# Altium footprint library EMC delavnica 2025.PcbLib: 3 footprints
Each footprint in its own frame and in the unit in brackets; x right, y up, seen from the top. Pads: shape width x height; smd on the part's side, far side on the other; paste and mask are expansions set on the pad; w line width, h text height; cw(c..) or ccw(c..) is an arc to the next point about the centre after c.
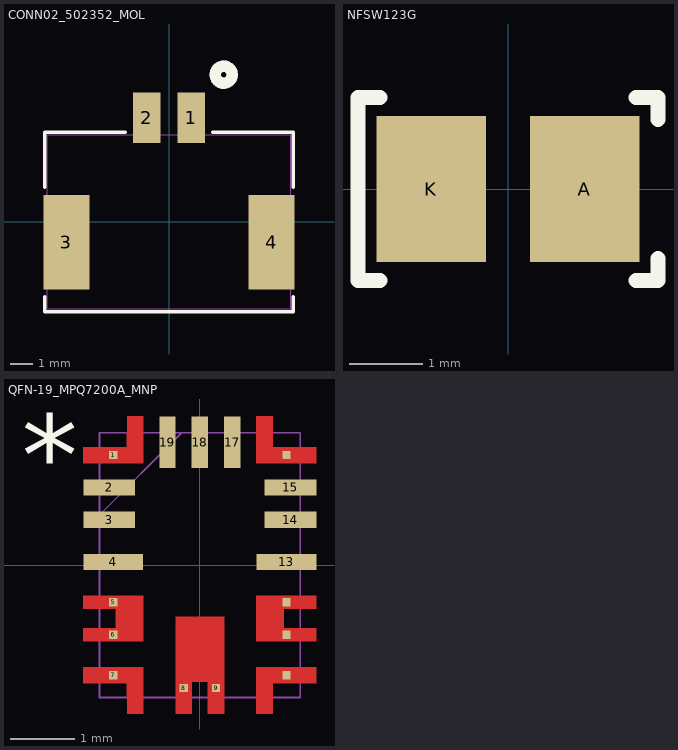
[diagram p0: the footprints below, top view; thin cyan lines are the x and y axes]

## CONN02_502352_MOL [mil]
pads (4):
  rect 49x89 smd paste+0 mask+0: 1(39.37,184.21) 2(-39.37,184.21)
  rect 81x167 smd paste-83.5 mask-83.5: 3(-181.1,-35.48) 4(181.1,-35.48)
Top Overlay:
  circle w20: c96.46,259.84 r15
  lines w6: -219.5,-132.08 -219.5,-158.5 219.5,-158.5 219.5,-132.08 ; -219.5,61.12 -219.5,158.5 -76.97,158.5 ; 76.97,158.5 219.5,158.5 219.5,61.12
Mechanical 13:
  circle w20: c96.46,259.84 r15
  lines w1: -214.5,-153.5 -214.5,153.5 214.5,153.5 214.5,-153.5 -214.5,-153.5
3D body "5600200220.stp": height 314.96, standoff 0, extent -214.57,-155.91 214.57,204.33

## NFSW123G [mm]
pads (2):
  rect 1.5x2 smd: A(1.05,0) K(-1.05,0)
Top Overlay:
  lines w0.2: -1.75,-1.25 -2.05,-1.25 -2.05,-0.95 -2.05,1.25 -1.75,1.25 ; 1.75,-1.25 2.05,-1.25 2.05,-0.95 ; 1.75,1.25 2.05,1.25 2.05,0.95
3D body "KSE068683A.step": height 0.71, standoff 0.01, extent -1.5,-1 1.5,1

## QFN-19_MPQ7200A_MNP [mm]
pads (19):
  rect 0.127x0.127 smd paste-0.064 mask-0.064: 1(-1.337,1.7) 5(-1.337,-0.575) 6(-1.337,-1.075) 7(-1.337,-1.7) 8(-0.25,-1.9) 9(0.25,-1.9) 10(1.337,-1.7) 11(1.337,-1.075) 12(1.337,-0.575) 16(1.337,1.7)
  rect 0.8x0.25 smd paste+0 mask+0: 2(-1.4,1.2) 3(-1.4,0.7) 14(1.4,0.7) 15(1.4,1.2)
  rect 0.925x0.25 smd paste+0 mask+0: 4(-1.337,0.05) 13(1.337,0.05)
  rect 0.25x0.8 smd paste+0 mask+0: 17(0.5,1.9) 18(0,1.9) 19(-0.5,1.9)
Top Layer:
  region: -1.125,-1.825 -1.799,-1.825 -1.799,-1.575 -0.874,-1.575 -0.875,-2.3 -1.125,-2.3
  region: 0.874,-0.475 1.799,-0.475 1.799,-0.675 1.299,-0.675 1.299,-0.975 1.799,-0.975 1.799,-1.175 0.874,-1.175
  region: 1.125,1.825 1.799,1.825 1.799,1.575 0.874,1.575 0.875,2.3 1.125,2.3
  region: 1.125,-1.825 1.799,-1.825 1.799,-1.575 0.874,-1.575 0.875,-2.3 1.125,-2.3
  region: -1.125,1.825 -1.799,1.825 -1.799,1.575 -0.874,1.575 -0.875,2.3 -1.125,2.3
  region: -0.874,-0.475 -1.799,-0.475 -1.799,-0.675 -1.299,-0.675 -1.299,-0.975 -1.799,-0.975 -1.799,-1.175 -0.874,-1.175
  region: -0.125,-2.3 -0.375,-2.3 -0.375,-0.8 0.375,-0.8 0.375,-2.3 0.125,-2.3 0.125,-1.8 -0.125,-1.8
Top Overlay:
  text "*" at -2.752,1.065 h1.27
Top Paste:
  region: -1.125,1.825 -1.799,1.825 -1.799,1.575 -0.874,1.575 -0.875,2.3 -1.125,2.3
  region: 1.125,1.825 1.799,1.825 1.799,1.575 0.874,1.575 0.875,2.3 1.125,2.3
  region: 0.874,-0.475 1.799,-0.475 1.799,-0.675 1.299,-0.675 1.299,-0.975 1.799,-0.975 1.799,-1.175 0.874,-1.175
  region: 1.125,-1.825 1.799,-1.825 1.799,-1.575 0.874,-1.575 0.875,-2.3 1.125,-2.3
  region: -0.125,-2.3 -0.375,-2.3 -0.375,-0.8 0.375,-0.8 0.375,-2.3 0.125,-2.3 0.125,-1.8 -0.125,-1.8
  region: -1.125,-1.825 -1.799,-1.825 -1.799,-1.575 -0.874,-1.575 -0.875,-2.3 -1.125,-2.3
  region: -0.874,-0.475 -1.799,-0.475 -1.799,-0.675 -1.299,-0.675 -1.299,-0.975 -1.799,-0.975 -1.799,-1.175 -0.874,-1.175
Top Solder:
  region: -0.874,-0.475 -1.799,-0.475 -1.799,-0.675 -1.299,-0.675 -1.299,-0.975 -1.799,-0.975 -1.799,-1.175 -0.874,-1.175
  region: -1.125,1.825 -1.799,1.825 -1.799,1.575 -0.874,1.575 -0.875,2.3 -1.125,2.3
  region: 1.125,1.825 1.799,1.825 1.799,1.575 0.874,1.575 0.875,2.3 1.125,2.3
  region: 0.874,-0.475 1.799,-0.475 1.799,-0.675 1.299,-0.675 1.299,-0.975 1.799,-0.975 1.799,-1.175 0.874,-1.175
  region: 1.125,-1.825 1.799,-1.825 1.799,-1.575 0.874,-1.575 0.875,-2.3 1.125,-2.3
  region: -0.125,-2.3 -0.375,-2.3 -0.375,-0.8 0.375,-0.8 0.375,-2.3 0.125,-2.3 0.125,-1.8 -0.125,-1.8
  region: -1.125,-1.825 -1.799,-1.825 -1.799,-1.575 -0.874,-1.575 -0.875,-2.3 -1.125,-2.3
Mechanical 13:
  lines w0.025: -1.549,0.775 -0.279,2.045 ; -1.549,-2.045 1.549,-2.045 1.549,2.045 -1.549,2.045 -1.549,-2.045
  text "*" at -2.545,1.065 h1.27
3D body "MPQ7200AGLE-AEC1.step": height 0.85, standoff 0, extent -1.5,-2 1.5,2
